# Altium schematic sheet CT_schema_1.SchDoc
size 383 x 258 mm
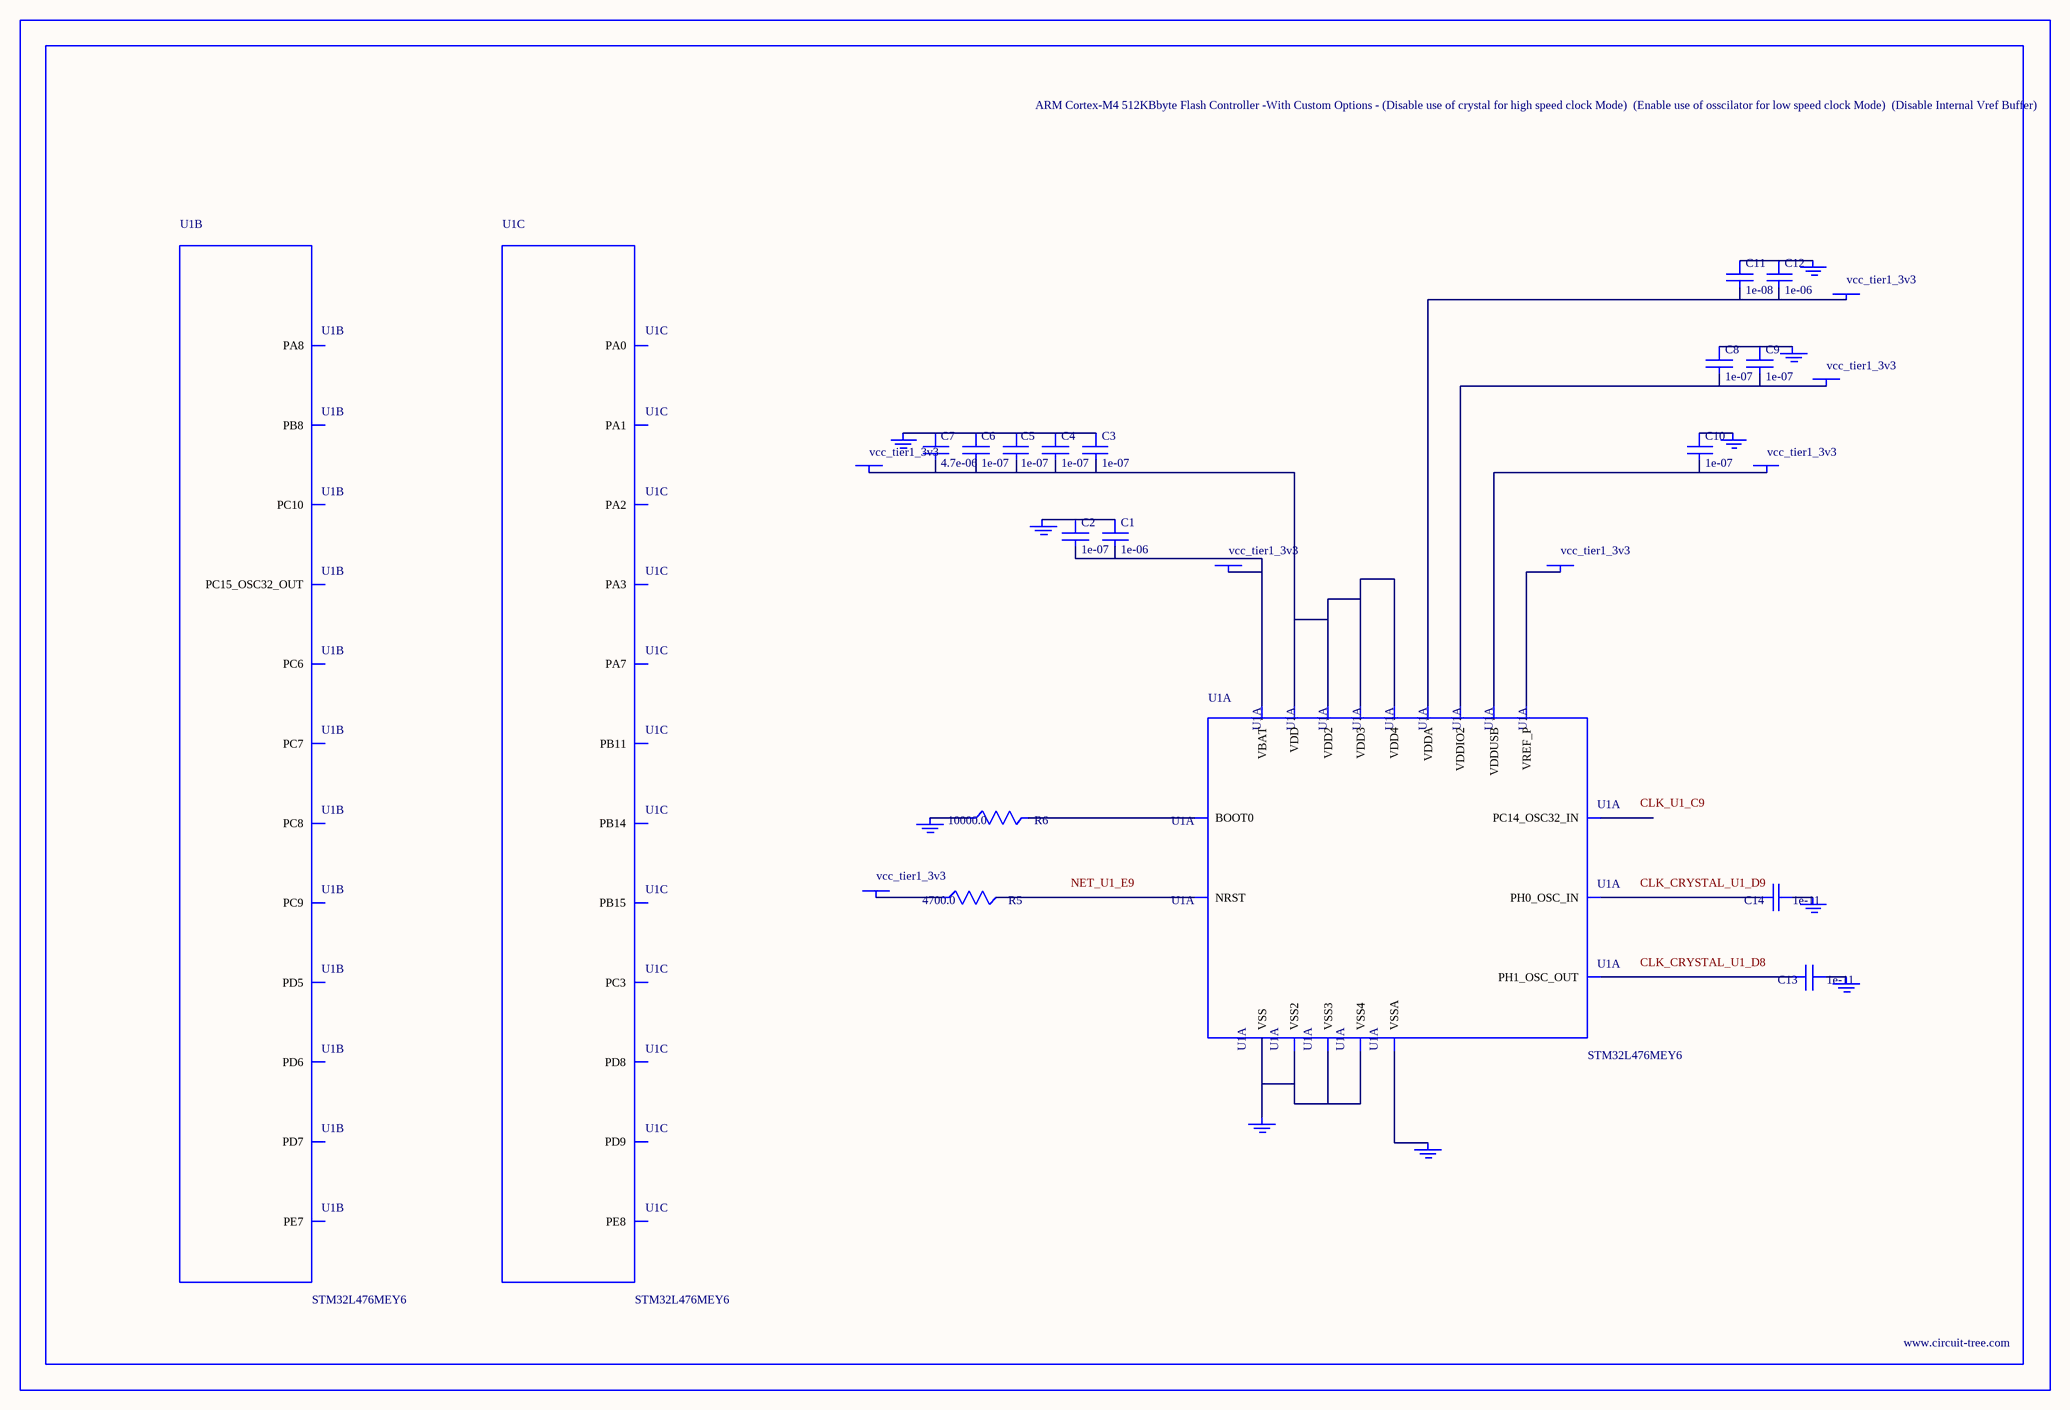
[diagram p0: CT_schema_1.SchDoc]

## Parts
BORDER0  (no value)
C1  1e-06  [C0603]
C2  1e-07  [C0603]
C3  1e-07  [C0603]
C4  1e-07  [C0603]
C5  1e-07  [C0603]
C6  1e-07  [C0603]
C7  4.7e-06  [C0603]
C8  1e-07  [C0603]
C9  1e-07  [C0603]
C10  1e-07  [C0603]
C11  1e-08  [C0603]
C12  1e-06  [C0603]
C13  1e-11  [C0402]
C14  1e-11  [C0402]
GND_INSTANCE_0_0  (no value)
GND_INSTANCE_0_1  (no value)
GND_INSTANCE_0_2  (no value)
GND_INSTANCE_0_3  (no value)
GND_INSTANCE_0_4  (no value)
GND_INSTANCE_0_5  (no value)
GND_INSTANCE_0_6  (no value)
GND_INSTANCE_0_7  (no value)
GND_INSTANCE_0_8  (no value)
GND_INSTANCE_0_9  (no value)
POWER_INSTANCE_0_0  vcc_tier1_3v3
POWER_INSTANCE_0_1  vcc_tier1_3v3
POWER_INSTANCE_0_2  vcc_tier1_3v3
POWER_INSTANCE_0_3  vcc_tier1_3v3
POWER_INSTANCE_0_4  vcc_tier1_3v3
POWER_INSTANCE_0_5  vcc_tier1_3v3
POWER_INSTANCE_0_6  vcc_tier1_3v3
R5  4700.0  [R0603]
R6  10000.0  [R0603]
U1  STM32L476MEY6  [WLCSP81]  (parts A,B,C of 9)

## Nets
NetC1_1: C1.1 C2.1 GND_INSTANCE_0_0.0(GND)
NetC1_2: C1.2 C2.2 POWER_INSTANCE_0_0.0(PWR) U1.B9(VBAT)
NetC3_1: C3.1 C4.1 C5.1 C6.1 C7.1 GND_INSTANCE_0_1.0(GND)
NetC3_2: C3.2 C4.2 C5.2 C6.2 C7.2 POWER_INSTANCE_0_1.0(PWR) U1.A9(VDD) U1.E4(VDD2) U1.J1(VDD3) U1.J8(VDD4)
NetC8_1: C8.1 C9.1 GND_INSTANCE_0_2.0(GND)
NetC8_2: C8.2 C9.2 POWER_INSTANCE_0_2.0(PWR) U1.B6(VDDIO2)
NetC10_1: C10.1 GND_INSTANCE_0_4.0(GND)
NetC10_2: C10.2 POWER_INSTANCE_0_3.0(PWR) U1.A1(VDDUSB)
NetC11_1: C11.1 C12.1 GND_INSTANCE_0_5.0(GND)
NetC11_2: C11.2 C12.2 POWER_INSTANCE_0_4.0(PWR) U1.H9(VDDA)
NetC13_1: C13.1 GND_INSTANCE_0_6.0(GND)
NetC13_2: C13.2 U1.D8(PH1_OSC_OUT)
NetC14_1: C14.1 GND_INSTANCE_0_7.0(GND)
NetC14_2: C14.2 U1.D9(PH0_OSC_IN)
NetGND_INSTANCE_0_3_0: GND_INSTANCE_0_3.0(GND) R6.1
NetGND_INSTANCE_0_8_0: GND_INSTANCE_0_8.0(GND) U1.G9(VSSA)
NetGND_INSTANCE_0_9_0: GND_INSTANCE_0_9.0(GND) U1.A8(VSS) U1.B1(VSS2) U1.J2(VSS3) U1.J9(VSS4)
NetPOWER_INSTANCE_0_5_0: POWER_INSTANCE_0_5.0(PWR) U1.G8(VREF_P)
NetPOWER_INSTANCE_0_6_0: POWER_INSTANCE_0_6.0(PWR) R5.1
NetR5_2: R5.2 U1.E9(NRST)
NetR6_2: R6.2 U1.D7(BOOT0)

Not connected (* = marked no-connect by the designer): U1 C8(PC15_OSC32_OUT) C9(PC14_OSC32_IN) D3(PC10) D4(PD5) D5(PD6) D6(PD7) E1(PC9) E2(PA8) E6(PE7) E7(PB8) F1(PC7) F2(PC8) F3(PC6) F4(PD9) F5(PD8) F6(PE8) G1(PB15) G2(PB14) G3(PB11) G4(PA1) G6(PA2) G7(PC3) H4(PA7) H7(PA3) H8(PA0)

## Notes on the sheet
- Labels drawn without touching a wire or pin: CLK_CRYSTAL_U1_D8, CLK_CRYSTAL_U1_D9, CLK_U1_C9, NET_U1_E9

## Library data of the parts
BORDER0 = BORDER_PAGE0
C1 C12 = C0603C105K3RACTU
C2-C6 C8-C10 = 06035C104K4Z2A
C7 = GRM188R6YA475KE15D
C11 = 06035C103K4Z2A
C13 C14 = C0402C100K3GACTU
GND_INSTANCE_0_0-GND_INSTANCE_0_9 = GND
POWER_INSTANCE_0_0-POWER_INSTANCE_0_6 = PWR
R5 = RC0603JR-074K7L
R6 = RC0603JR-0710KL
